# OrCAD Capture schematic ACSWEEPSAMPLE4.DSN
size A
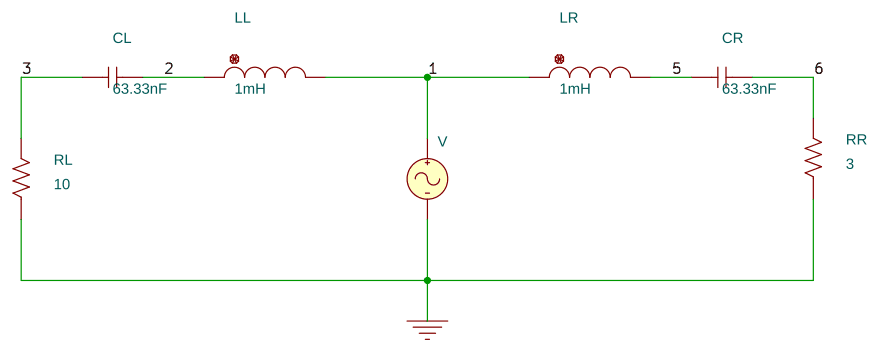
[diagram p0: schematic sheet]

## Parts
CL  63.33nF  [RAD/CK05]
CR  63.33nF  [RAD/CK05]
LL  1mH  [DISC/.350x.175/LS.200x.100/.034]
LR  1mH  [DISC/.350x.175/LS.200x.100/.034]
RL  10  [AX/RC05]
RR  3  [AX/RC05]
V  VAC

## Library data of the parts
CL CR = C
LL LR = L
RL RR = R
V = VAC

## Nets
0: RL.1 RR.1 V.2(-)
1: LL.2 LR.1 V.1(+)
2: CL.2 LL.1
3: CL.1 RL.2
5: CR.1 LR.2
6: CR.2 RR.2
